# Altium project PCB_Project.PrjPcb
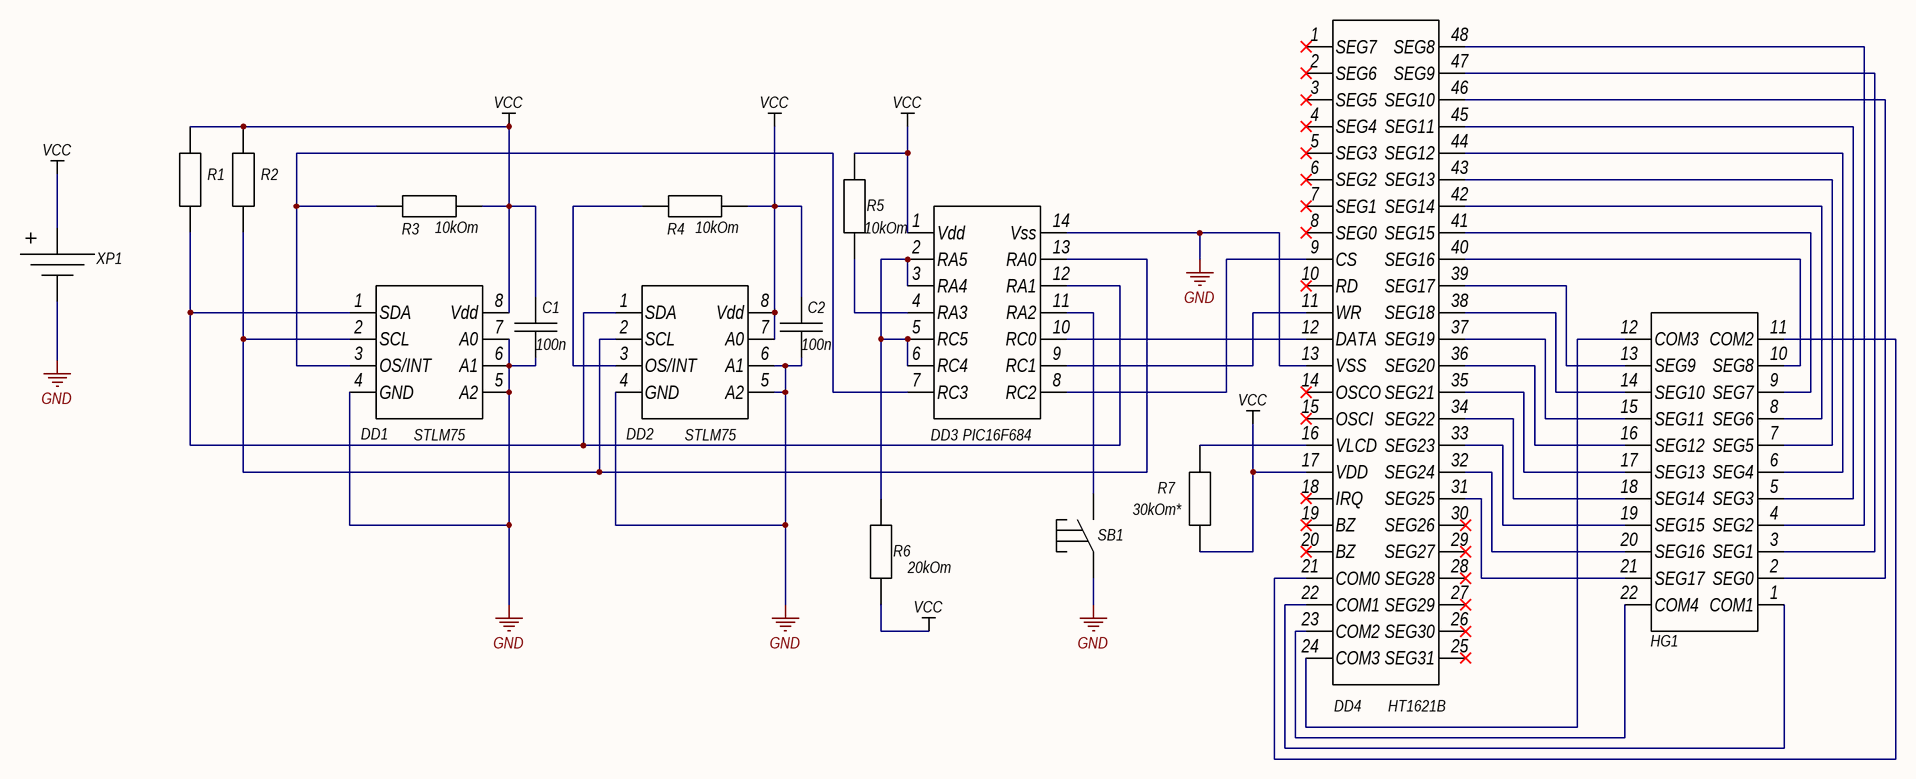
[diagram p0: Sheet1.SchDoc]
1 sheet, 16 parts. Net scope: global (net labels, ports and power ports of the same name join across sheets).
Board file: PCB1.PcbDoc

## Sheet Sheet1.SchDoc
size 420 x 297 mm; Date: 26.09.2021; CompanyName: "РадиоКот"; Разраб.: Романович Н.А.; Обозначение документа: АБВГ.123456.001 Э3; Перв. применение: АБВГ.123456.000; Наименование изделия 1: Цифровой термометр с ЖКИ; Наименование изделия 2: Схема электрическая; Наименование изделия 3: принципиальная

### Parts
C1  100n  [Capasitors]
C2  100n  [Capasitors]
DD1  STLM75  [MSOP8]
DD2  STLM75  [MSOP8]
DD3  PIC16F684  [SOIC14]
DD4  HT1621B  [SSOP48(300mil)]
HG1  LCD_gaz  [LCD_gaz]  (value not drawn)
R1  RES  [Res0.25W]  (value not drawn)
R2  RES  [Res0.25W]  (value not drawn)
R3  10kOm  [Res0.25W]
R4  10kOm  [Res0.25W]
R5  10kOm  [Res0.25W]
R6  20kOm  [0805]
R7  30kOm*  [0805]
SB1  Switch_6x6  [Switch_6x6]  (value not drawn)
XP1  Battery  [Battery_2032]  (value not drawn)

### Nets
GND: C1.1 C2.1 DD1.4(GND) DD1.5(A2) DD1.6(A1) DD1.7(A0) DD2.4(GND) DD2.5(A2) DD2.6(A1) DD3.14(Vss) DD4.13(VSS) SB1.1 XP1.1
VCC: C1.2 C2.2 DD1.8(Vdd) DD2.7(A0) DD2.8(Vdd) DD3.1(Vdd) DD4.17(VDD) R1.2 R2.2 R3.1 R4.1 R5.2 R6.1 R7.1 XP1.2
NetDD1_1: DD1.1(SDA) DD2.1(SDA) DD3.12(RA1) R1.1
NetDD1_2: DD1.2(SCL) DD2.2(SCL) DD3.13(RA0) R2.1
NetDD1_3: DD1.3(OS/INT) DD3.7(RC3) R3.2
NetDD2_3: DD2.3(OS/INT) R4.2
NetDD3_2: DD3.2(RA5) DD3.3(RA4) DD3.5(RC5) DD3.6(RC4) R6.2
NetDD3_4: DD3.4(RA3) R5.1
NetDD3_8: DD3.8(RC2) DD4.9(CS)
NetDD3_9: DD3.9(RC1) DD4.11(WR)
NetDD3_10: DD3.10(RC0) DD4.12(DATA)
NetDD3_11: DD3.11(RA2) SB1.2
NetDD4_16: DD4.16(VLCD) R7.2
NetDD4_21: DD4.21(COM0) HG1.11(COM2)
NetDD4_22: DD4.22(COM1) HG1.1(COM1)
NetDD4_23: DD4.23(COM2) HG1.22(COM4)
NetDD4_24: DD4.24(COM3) HG1.12(COM3)
NetDD4_31: DD4.31(SEG25) HG1.21(SEG17)
NetDD4_32: DD4.32(SEG24) HG1.20(SEG16)
NetDD4_33: DD4.33(SEG23) HG1.19(SEG15)
NetDD4_34: DD4.34(SEG22) HG1.18(SEG14)
NetDD4_35: DD4.35(SEG21) HG1.17(SEG13)
NetDD4_36: DD4.36(SEG20) HG1.16(SEG12)
NetDD4_37: DD4.37(SEG19) HG1.15(SEG11)
NetDD4_38: DD4.38(SEG18) HG1.14(SEG10)
NetDD4_39: DD4.39(SEG17) HG1.13(SEG9)
NetDD4_40: DD4.40(SEG16) HG1.10(SEG8)
NetDD4_41: DD4.41(SEG15) HG1.9(SEG7)
NetDD4_42: DD4.42(SEG14) HG1.8(SEG6)
NetDD4_43: DD4.43(SEG13) HG1.7(SEG5)
NetDD4_44: DD4.44(SEG12) HG1.6(SEG4)
NetDD4_45: DD4.45(SEG11) HG1.5(SEG3)
NetDD4_46: DD4.46(SEG10) HG1.2(SEG0)
NetDD4_47: DD4.47(SEG9) HG1.3(SEG1)
NetDD4_48: DD4.48(SEG8) HG1.4(SEG2)

Not connected (* = marked no-connect by the designer): DD4 1(SEG7)* 2(SEG6)* 3(SEG5)* 4(SEG4)* 5(SEG3)* 6(SEG2)* 7(SEG1)* 8(SEG0)* 10(RD)* 14(OSCO)* 15(OSCI)* 18(IRQ)* 19(BZ)* 20(BZ)* 25(SEG31)* 26(SEG30)* 27(SEG29)* 28(SEG28)* 29(SEG27)* 30(SEG26)*; SB1 3 4

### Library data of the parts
C1 C2 = CAP
R3-R7 = RES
